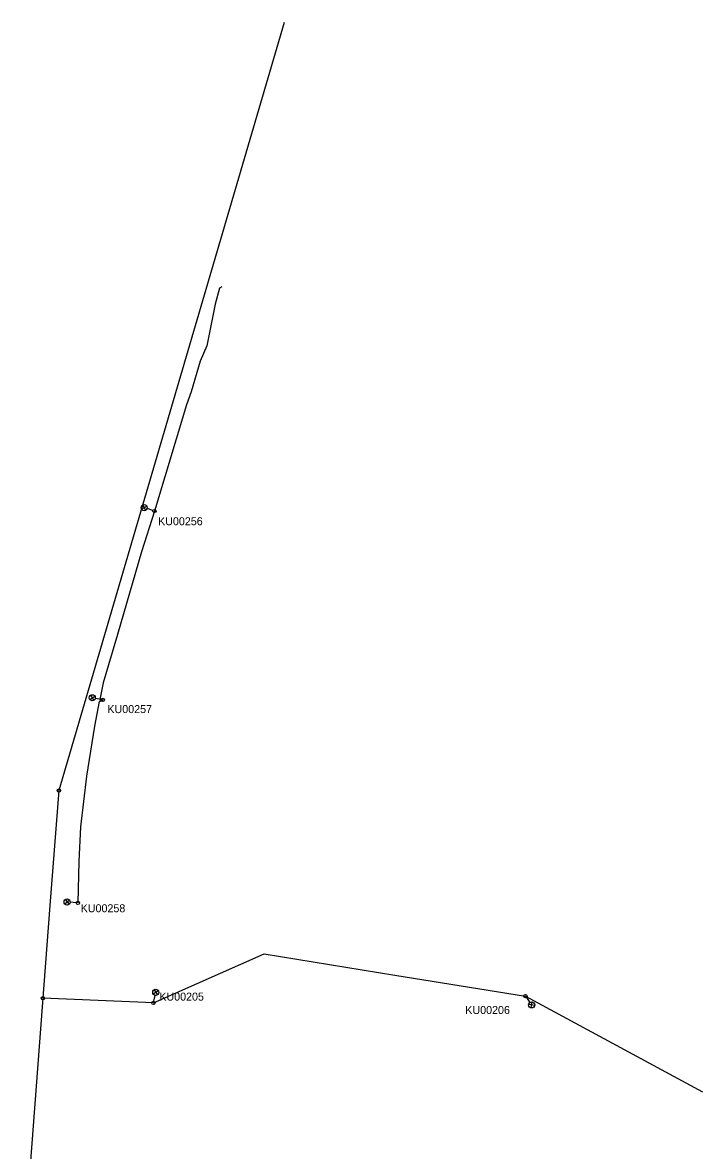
# Model space of a CAD drawing. Extents: x -727894 to -727647, y -1062988 to -1062565.
# Drawn here: x -727774.3 to -727646.9, y -1062776.8 to -1062565.4 of the extents above; entities that cross this region are included whole.
import ezdxf

# ---------------------------------------------------------------- set-up
doc = ezdxf.new("R2010")
doc.units = 0
for name, color, linetype in [('Kabelove_vedeni_vrchni', 7, 'Continuous'), ('Kabelove_vedeni_zemni', 7, 'Continuous'), ('Pomocny_stozar', 7, 'Continuous'), ('Verejne_osvetleni', 7, 'Continuous'), ('Verejne_osvetleni_popis', 7, 'Continuous')]:
    doc.layers.add(name, color=color, linetype=linetype)

msp = doc.modelspace()

# ---------------------------------------------------------------- linework, layer by layer
at = {"layer": 'Kabelove_vedeni_vrchni'}
for points in [[(-727725.31, -1062565.44), (-727767.53, -1062709.38), (-727769.22, -1062730.91), (-727774.35, -1062798.61)], [(-727749.81, -1062749.17), (-727729.04, -1062739.99), (-727704.56, -1062743.94), (-727680.08, -1062747.89)], [(-727749.81, -1062749.17), (-727770.53, -1062748.29)], [(-727680.08, -1062747.89), (-727646.89, -1062765.86)]]:
    msp.add_lwpolyline(points, dxfattribs=at)
at = {"layer": 'Kabelove_vedeni_zemni'}
for points in [[(-727736.96, -1062614.95), (-727737.43, -1062615.22), (-727738.22, -1062618.23), (-727739.79, -1062626.05), (-727741.02, -1062628.88), (-727742.71, -1062634.67), (-727743.62, -1062637.07), (-727749.62, -1062656.98)], [(-727749.62, -1062656.98), (-727752.04, -1062664.64), (-727756.52, -1062680.13), (-727759.25, -1062689.2), (-727759.89, -1062692.28), (-727759.3, -1062692.39)], [(-727759.3, -1062692.39), (-727759.77, -1062692.71), (-727759.97, -1062692.67), (-727760.86, -1062697.29), (-727762.38, -1062706.7), (-727763.47, -1062716.18), (-727763.79, -1062722.68), (-727763.97, -1062730.43)]]:
    msp.add_lwpolyline(points, dxfattribs=at)
at = {"layer": 'Pomocny_stozar'}
for centre in [(-727767.53, -1062709.38), (-727770.53, -1062748.29)]:
    msp.add_circle(centre, 0.305, dxfattribs=at)
at = {"layer": 'Verejne_osvetleni'}
for p, q in [((-727752.06, -1062656.63), (-727751.04, -1062656.1)), ((-727751.81, -1062655.85), (-727751.29, -1062656.87)), ((-727749.91, -1062656.89), (-727751, -1062656.54)), ((-727761.76, -1062692.31), (-727760.81, -1062691.67)), ((-727761.6, -1062691.51), (-727760.97, -1062692.47)), ((-727759.6, -1062692.33), (-727760.72, -1062692.1)), ((-727766.43, -1062730.61), (-727765.55, -1062729.88)), ((-727766.36, -1062729.81), (-727765.62, -1062730.69)), ((-727764.27, -1062730.4), (-727765.42, -1062730.3)), ((-727748.9, -1062746.88), (-727749.86, -1062747.5)), ((-727749.74, -1062748.87), (-727749.5, -1062747.75)), ((-727749.69, -1062746.71), (-727749.07, -1062747.67)), ((-727679.9, -1062748.14), (-727679.23, -1062749.07)), ((-727678.33, -1062749.63), (-727679.46, -1062749.44)), ((-727678.99, -1062750.1), (-727678.81, -1062748.97))]:
    msp.add_line(p, q, dxfattribs=at)
for centre, radius in [((-727751.55, -1062656.36), 0.574), ((-727749.62, -1062656.98), 0.306), ((-727761.29, -1062691.99), 0.574), ((-727759.3, -1062692.39), 0.306), ((-727765.99, -1062730.25), 0.574), ((-727763.97, -1062730.43), 0.306), ((-727749.38, -1062747.19), 0.574), ((-727680.08, -1062747.89), 0.306), ((-727749.81, -1062749.17), 0.306), ((-727678.9, -1062749.54), 0.574)]:
    msp.add_circle(centre, radius, dxfattribs=at)

# ---------------------------------------------------------------- texts
at = {"layer": 'Verejne_osvetleni_popis'}
for s, p in [('KU00256', (-727748.94, -1062659.65)), ('KU00257', (-727758.44, -1062694.85)), ('KU00258', (-727763.45, -1062732.18)), ('KU00205', (-727748.71, -1062748.74)), ('KU00206', (-727691.35, -1062751.25))]:
    msp.add_text(s, height=1.5, dxfattribs=at).set_placement(p)

doc.saveas('drawing.dxf')
